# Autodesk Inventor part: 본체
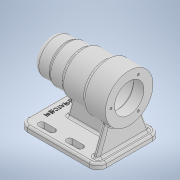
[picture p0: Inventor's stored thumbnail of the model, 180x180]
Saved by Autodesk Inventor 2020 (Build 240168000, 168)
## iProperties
Created: 2021-10
Part Number: 본체
Material: 일반
Document SubType Name: Modeling
Designer: user
Density: 1 g/cm^3
Appearance: 기본값
Author: user
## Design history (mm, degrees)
sketch "스케치1"
  geometry: L1 (0, 0)-(0, 34); L2 (0, 34)-(-32, 34); L3 (-32, 34)-(-32, 30); L4 (-32, 30)-(-66, 30); L5 (-66, 30)-(-66, 27); L6 (-66, 27)-(-88, 27); L7 (-88, 27)-(-88, 25); L8 (-88, 25)-(-112, 25); L9 (-112, 25)-(-112, 0); L10 (-112, 0)-(0, 0)
  constraints: 20 end point, 9 perpendicular, 1 vertical
  dimensions: "d0" = 34 distance of L1.start L1.end; "d1" = 112 distance of L9.end L1.start; "d2" = 24 distance between parallel lines of L9 L7; "d4" = 46 distance between parallel lines of L9 L5; "d5" = 80 distance between parallel lines of L9 L3; "d6" = 60 diameter of L4 L10; "d7" = 54 diameter of L6 L10; "d8" = 50 diameter of L8 L10
revolve "회전1" sketch "스케치1" stored, may be unused: angle "d9" = 90 deg
fillet "모깎기1" dims "d10" = 8
sketch "스케치2"
  geometry: C1 r 21 at (0, 0); 1 further point
  constraints: 1 centre point, 1 coincident
  dimensions: "d11" = 42 diameter of C1
extrude "돌출1" cut sketch "스케치2" distance "d12" = 15; taper "d13" = 0 deg
sketch "스케치3"
  geometry: C1 r 24 at (0, 0); 1 further point
  constraints: 1 centre point, 1 coincident
  dimensions: "d14" = 48 diameter of C1
extrude "돌출2" cut sketch "스케치3" distance "d15" = 54; taper "d16" = 0 deg
sketch "스케치4"
  geometry: C1 r 21 at (0, 0); 1 further point
  constraints: 1 centre point, 1 coincident
  dimensions: "d17" = 42 diameter of C1
extrude "돌출3" cut sketch "스케치4" distance "d18" = 12; taper "d19" = 0 deg
sketch "스케치5"
  geometry: C1 r 17.5 at (0, 0); 1 further point
  constraints: 1 centre point, 1 coincident
  dimensions: "d20" = 35 diameter of C1
extrude "돌출4" cut sketch "스케치5" distance "d21" = 18; taper "d22" = 0 deg
sketch "스케치6"
  geometry: C1 r 16 at (0, 0); 1 further point
  constraints: 1 centre point, 1 coincident
  dimensions: "d23" = 32 diameter of C1
extrude "돌출5" cut sketch "스케치6" distance "d24" = 4; taper "d25" = 0 deg
sketch "스케치7"
  geometry: C1 r 10.5 at (0, 0); 1 further point
  constraints: 1 centre point, 1 coincident
  dimensions: "d26" = 21 diameter of C1
extrude "돌출6" cut sketch "스케치7" distance "d27" = 3; taper "d28" = 0 deg
fillet "모깎기2" dims "d29" = 0.3
fillet "모깎기3" dims "d30" = 3
sketch "스케치8"
  geometry: 2 further points
  constraints: 1 horizontal alignment
  dimensions: "d31" = 26 distance of point (-26, 0) point (0, 0)
hole "구멍1" sketch "스케치8" at (-26, 0) diameter "d32" = 3.242; stored, may be unused: countersink angle "d36" = 90 deg, drill point angle "d38" = 118 deg; dims "d33" = 8, "d34" = 4, "d35" = 2, "d37" = 11
node "작업 평면1"
sketch "스케치9"
  geometry: L1 (112, -45)-(0, -45); L2 (0, -45)-(0, 45); L3 (0, 45)-(112, 45); L4 (112, 45)-(112, -45); 2 further points
  constraints: 8 end point, 2 midpoint, 2 parallel, 1 horizontal, 1 horizontal alignment, 1 perpendicular
  dimensions: "d43" = 112 distance of L2.end L3.end; "d44" = 90 distance of L1.end L2.end
extrude "돌출7" join sketch "스케치9" distance "d45" = 8; taper "d46" = 0 deg
fillet "모깎기4" dims "d47" = 12
sketch "스케치10"
  geometry: L1 (-8, 4)-(-85, 4); L2 (-85, 4)-(-85, -4); L3 (-85, -4)-(-8, -4); L4 (-8, -4)-(-8, 4); L5 (-8, 4)-(-85, -4); L6 (-85, 4)-(-8, -4); L7 (0, -33)-(0, 33) reference; 4 further points
  constraints: 12 end point, 4 midpoint, 2 parallel, 1 horizontal, 1 horizontal alignment, 1 perpendicular
  dimensions: "d48" = 8 distance between parallel lines of L7 L4; "d49" = 8 distance of L3.end L1.start; "d50" = 77 distance of L1.start L1.end
extrude "돌출8" join sketch "스케치10" stored distance "d51" = 8; taper "d52" = 0 deg
feature "면 기울기1" dims angle "d53" = 15 deg
sketch "스케치11"
  geometry: L1 (-19.409, 37.342)-(-33, 0); L2 (27.409, 37.342)-(41, 0); L3 (-41, 0)-(-41, -8) reference; L4 (49, -8)-(49, 0) reference; L5 (-41, 0)-(-29, 0) reference; L6 (37, 0)-(49, 0) reference; L7 (37, 0)-(-29, 0) reference; L8 (0, 0)-(0, 28.236) reference; L9 (-29, 0)-(37, 0) reference; L10 (-41, 0)-(-29, 0) reference; L11 (8, 0)-(8, 28.236) reference; L12 (37, 0)-(49, 0) reference; A1 r 34 centre (4, 62) between (8, 28.236) and (0, 28.236) reference; 2 further points
  constraints: 4 end point, 2 point on circle, 2 point on line
  dimensions: "d54" = 8 distance from line of L3 L1.end; "d55" = 8 distance from line of L4 L2.end; "d56" = 110 deg angle of L5 L1; "d57" = 110 deg angle of L6 L2
extrude "돌출9" join sketch "스케치11" distance "d58" = 8; taper "d59" = 0 deg
sketch "스케치12"
  geometry: L1 (-92, 33)-(-77, 33); L2 (-92, 28.5)-(-77, 28.5); L3 (-77, 37.5)-(-92, 37.5); L4 (-112, 33)-(-112, -33) reference; L5 (-52, 33)-(-37, 33); L6 (-52, 28.5)-(-37, 28.5); L7 (-37, 37.5)-(-52, 37.5); A1 r 4.5 centre (-92, 33) between (-92, 37.5) and (-92, 28.5); A2 r 4.5 centre (-77, 33) between (-77, 28.5) and (-77, 37.5); A3 r 4.5 centre (-37, 33) between (-37, 28.5) and (-37, 37.5); A4 r 4.5 centre (-52, 33) between (-52, 37.5) and (-52, 28.5); 3 further points
  constraints: 16 end point, 8 point on circle, 8 tangent, 4 centre point, 2 horizontal, 2 midpoint, 2 parallel, 1 horizontal alignment
  dimensions: "d60" = 4.5 radius of A1; "d61" = 20 distance from line of L4 L1.start; "d62" = 15 distance of L1.start L1.end; "d63" = 33 vertical distance of point (0, 0) point (-84.5, 33); "d66" = 4.5 radius of A4; "d67" = 15 distance of L5.start L5.end; "d68" = 25 distance of L1.end L5.start
extrude "돌출10" cut sketch "스케치12" extent not by distance; stored distance "d64" = 74.369; taper "d65" = 0 deg
fillet "모깎기5" dims "d69" = 3
fillet "모깎기6" dims "d70" = 3
fillet "모깎기7" dims "d71" = 3
fillet "모깎기8" dims "d72" = 3
sketch "스케치13"
  geometry: L1 (-112, 33)-(-112, -33) reference; 2 further points
  constraints: 1 horizontal alignment, 1 other
  dimensions: "d73" = 12 distance from line of L1 point (-100, 0)
feature "엠보싱1" sketch "스케치13" dims "d74" = 0.5, "d75" = 0
node "솔리드1"
pattern_circular "원형 패턴1" dims angle "d40" = 360 deg
mirror "미러1"
feature "A9D066F2-1C7D-4E18-AEED-F7BC21143FA4" dims "d32" = 3.242, "d33" = 8, "d34" = 4, "d35" = 2, "d36" = 90 deg, "d37" = 11, "d38" = 118 deg
